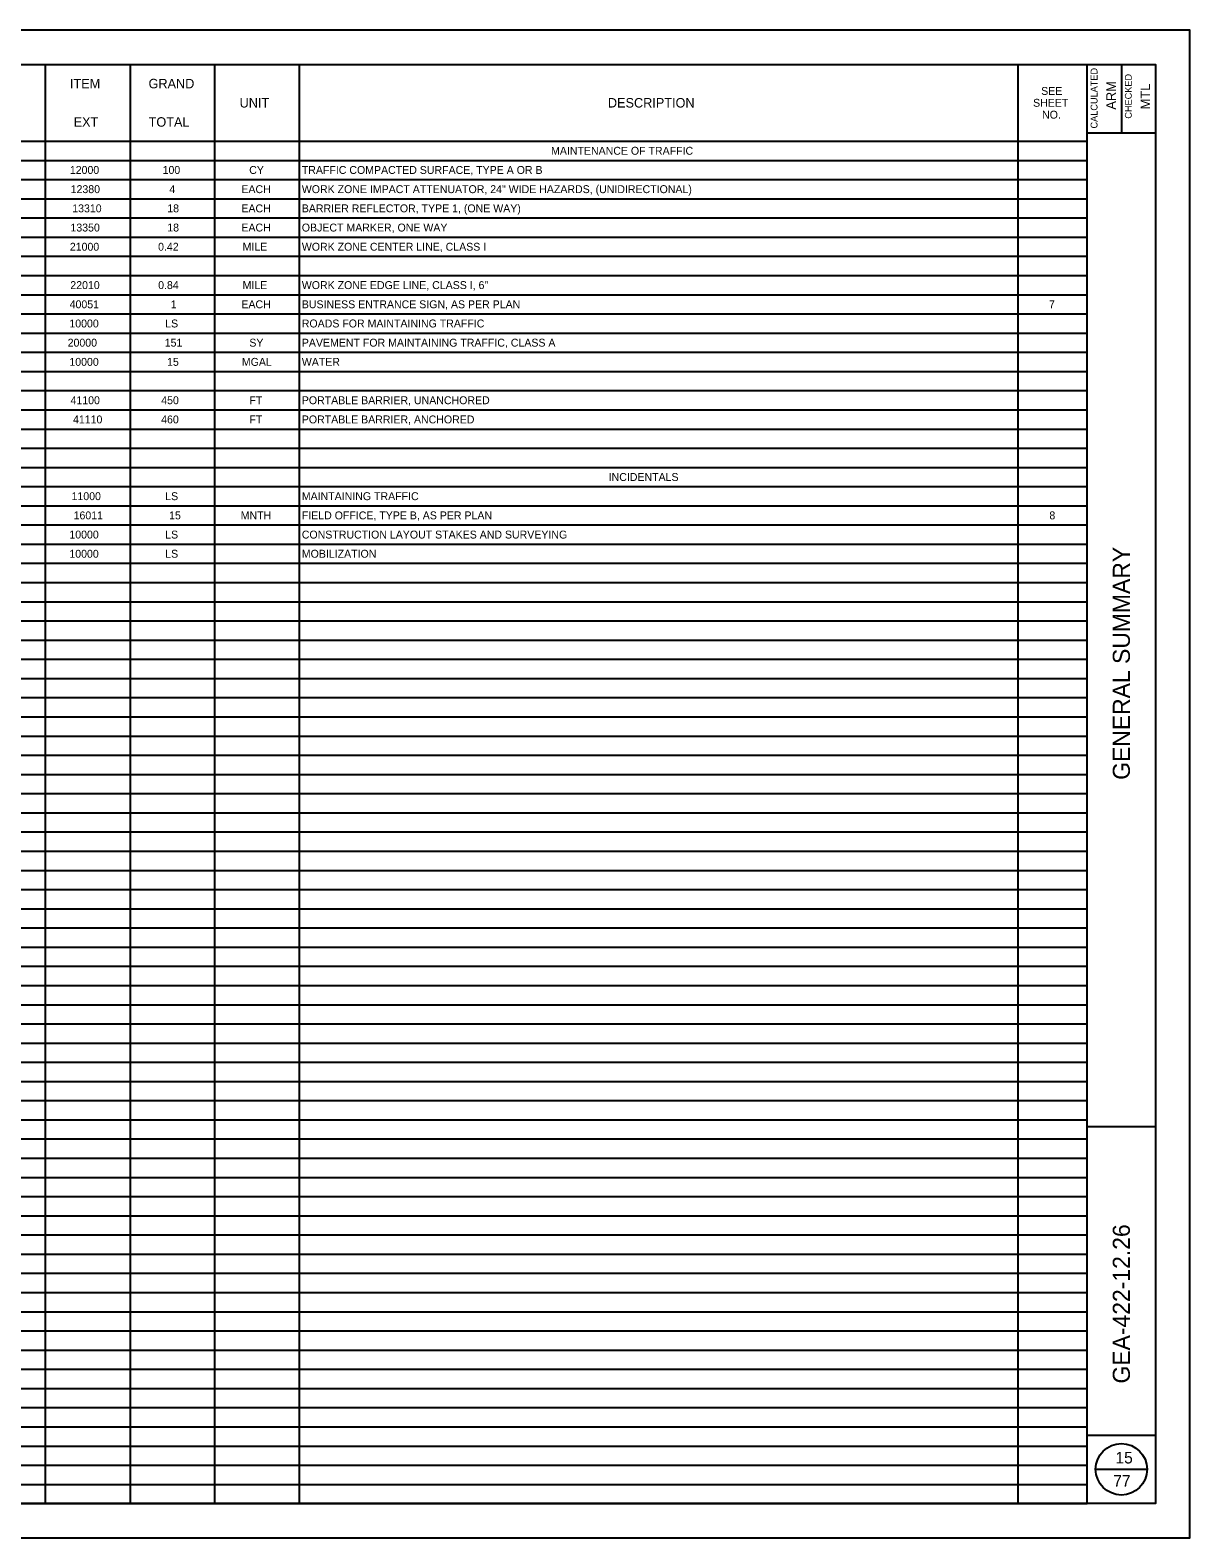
# Model space of a CAD drawing. Extents: x 0 to 34, y 0 to 23.1.
# Drawn here: x 17.07 to 34, y 0 to 22 of the extents above; entities that cross this region are included whole.
import ezdxf

# ---------------------------------------------------------------- set-up
doc = ezdxf.new("R2010")
doc.units = 0
for name, color, linetype in [('SH_Border', 7, 'Continuous'), ('SH_Cut_Line', 7, 'Continuous'), ('SH_Data', 7, 'Continuous'), ('SH_Text', 7, 'Continuous')]:
    doc.layers.add(name, color=color, linetype=linetype)

msp = doc.modelspace()

# ---------------------------------------------------------------- linework, layer by layer
at = {"layer": 'SH_Border'}
for p, q in [((32.5, 0.5), (32.5, 21.5)), ((33, 21.5), (33, 20.5)), ((32.5, 20.5), (33.5, 20.5)), ((32.5, 6), (33.5, 6)), ((32.5, 1.5), (33.5, 1.5))]:
    msp.add_line(p, q, dxfattribs=at)
msp.add_lwpolyline([(2, 21.5), (33.5, 21.5), (33.5, 0.5), (2, 0.5)], close=True, dxfattribs=at)
at = {"layer": 'SH_Cut_Line'}
msp.add_lwpolyline([(0, 0), (34, 0), (34, 22), (0, 22)], close=True, dxfattribs=at)
at = {"layer": 'SH_Data'}
msp.add_line((32.625, 1), (33.375, 1), dxfattribs=at)
msp.add_circle((33, 1), 0.375, dxfattribs=at)
at = {"layer": 'SH_Text'}
for p, q in [((2, 21.5), (32.5, 21.5)), ((17.299, 0.5), (17.299, 21.5)), ((18.535, 0.5), (18.535, 21.5)), ((19.77, 0.5), (19.77, 21.5)), ((21.005, 0.5), (21.005, 21.5)), ((31.495, 0.5), (31.495, 21.5)), ((32.5, 0.5), (32.5, 21.5)), ((14.055, 20.38), (32.5, 20.38)), ((19.77, 20.38), (32.5, 20.38)), ((2, 20.1), (32.5, 20.1)), ((2, 19.82), (32.5, 19.82)), ((2, 19.54), (32.5, 19.54)), ((2, 19.26), (32.5, 19.26)), ((2, 18.98), (32.5, 18.98)), ((2, 18.7), (32.5, 18.7)), ((2, 18.42), (32.5, 18.42)), ((2, 18.14), (32.5, 18.14)), ((2, 17.86), (32.5, 17.86)), ((2, 17.58), (32.5, 17.58)), ((2, 17.3), (32.5, 17.3)), ((2, 17.02), (32.5, 17.02)), ((2, 16.74), (32.5, 16.74)), ((2, 16.46), (32.5, 16.46)), ((2, 16.18), (32.5, 16.18)), ((2, 15.9), (32.5, 15.9)), ((2, 15.62), (32.5, 15.62)), ((2, 15.34), (32.5, 15.34)), ((2, 15.06), (32.5, 15.06)), ((2, 14.78), (32.5, 14.78)), ((2, 14.5), (32.5, 14.5)), ((2, 14.22), (32.5, 14.22)), ((2, 13.94), (32.5, 13.94)), ((2, 13.66), (32.5, 13.66)), ((2, 13.38), (32.5, 13.38)), ((2, 13.1), (32.5, 13.1)), ((2, 12.82), (32.5, 12.82)), ((2, 12.54), (32.5, 12.54)), ((2, 12.26), (32.5, 12.26)), ((2, 11.98), (32.5, 11.98)), ((2, 11.7), (32.5, 11.7)), ((2, 11.42), (32.5, 11.42)), ((2, 11.14), (32.5, 11.14)), ((2, 10.86), (32.5, 10.86)), ((2, 10.58), (32.5, 10.58)), ((2, 10.3), (32.5, 10.3)), ((2, 10.02), (32.5, 10.02)), ((2, 9.74), (32.5, 9.74)), ((2, 9.46), (32.5, 9.46)), ((2, 9.18), (32.5, 9.18)), ((2, 8.9), (32.5, 8.9)), ((2, 8.62), (32.5, 8.62)), ((2, 8.34), (32.5, 8.34)), ((2, 8.06), (32.5, 8.06)), ((2, 7.78), (32.5, 7.78)), ((2, 7.5), (32.5, 7.5)), ((2, 7.22), (32.5, 7.22)), ((2, 6.94), (32.5, 6.94)), ((2, 6.66), (32.5, 6.66)), ((2, 6.38), (32.5, 6.38)), ((2, 6.1), (32.5, 6.1)), ((2, 5.82), (32.5, 5.82)), ((2, 5.54), (32.5, 5.54)), ((2, 5.26), (32.5, 5.26)), ((2, 4.98), (32.5, 4.98)), ((2, 4.7), (32.5, 4.7)), ((2, 4.42), (32.5, 4.42)), ((2, 4.14), (32.5, 4.14)), ((2, 3.86), (32.5, 3.86)), ((2, 3.58), (32.5, 3.58)), ((2, 3.3), (32.5, 3.3)), ((2, 3.02), (32.5, 3.02)), ((2, 2.74), (32.5, 2.74)), ((2, 2.46), (32.5, 2.46)), ((2, 2.18), (32.5, 2.18)), ((2, 1.9), (32.5, 1.9)), ((2, 1.62), (32.5, 1.62)), ((2, 1.34), (32.5, 1.34)), ((2, 1.06), (32.5, 1.06)), ((2, 0.78), (32.5, 0.78)), ((2, 0.5), (32.5, 0.5))]:
    msp.add_line(p, q, dxfattribs=at)

# ---------------------------------------------------------------- texts
at = {"layer": 'SH_Data'}
for s, height, p in [('CALCULATED', 0.1, (32.652, 20.565)), ('CHECKED', 0.1, (33.152, 20.708)), ('ARM', 0.14, (32.92, 20.84)), ('MTL', 0.14, (33.42, 20.844)), ('GENERAL SUMMARY', 0.25, (33.125, 11.061)), ('GEA-422-12.26', 0.25, (33.125, 2.252))]:
    msp.add_text(s, height=height, rotation=90, dxfattribs=at).set_placement(p)
for s, p in [('15', (32.914, 1.085)), ('77', (32.882, 0.745))]:
    msp.add_text(s, height=0.17, dxfattribs=at).set_placement(p)
at = {"layer": 'SH_Text'}
for s, height, p in [('ITEM', 0.1384, (17.654, 21.151)), ('GRAND', 0.1384, (18.801, 21.151)), ('SEE', 0.1153, (31.83, 21.055)), ('UNIT', 0.1384, (20.13, 20.871)), ('DESCRIPTION', 0.13841, (25.506, 20.871)), ('SHEET', 0.1153, (31.712, 20.882)), ('EXT', 0.1384, (17.707, 20.591)), ('TOTAL', 0.1384, (18.802, 20.591)), ('NO.', 0.1153, (31.843, 20.709)), ('MAINTENANCE OF TRAFFIC', 0.11534, (24.676, 20.182)), ('12000', 0.1153, (17.652, 19.902)), ('100', 0.1153, (19.006, 19.902)), ('CY', 0.1153, (20.27, 19.902)), ('TRAFFIC COMPACTED SURFACE, TYPE A OR B ', 0.11534, (21.038, 19.902)), ('12380', 0.1153, (17.664, 19.622)), ('12380', 0.1153, (17.664, 19.622)), ('4', 0.115, (19.104, 19.622)), ('EACH', 0.1153, (20.156, 19.622)), ('WORK ZONE IMPACT ATTENUATOR, 24" WIDE HAZARDS, (UNIDIRECTIONAL) ', 0.11534, (21.038, 19.622)), ('WORK ZONE IMPACT ATTENUATOR, 24" WIDE HAZARDS, (UNIDIRECTIONAL) ', 0.11534, (21.038, 19.622)), ('13310', 0.1153, (17.687, 19.342)), ('18', 0.1153, (19.074, 19.342)), ('EACH', 0.1153, (20.156, 19.342)), ('BARRIER REFLECTOR, TYPE 1, (ONE WAY)', 0.11534, (21.038, 19.342)), ('BARRIER REFLECTOR, TYPE 1, (ONE WAY)', 0.11534, (21.038, 19.342)), ('13350', 0.1153, (17.661, 19.062)), ('18', 0.1153, (19.074, 19.062)), ('EACH', 0.1153, (20.156, 19.062)), ('OBJECT MARKER, ONE WAY ', 0.11534, (21.038, 19.062)), ('21000', 0.1153, (17.652, 18.782)), ('0.42', 0.1153, (18.94, 18.782)), ('MILE', 0.1153, (20.174, 18.782)), ('WORK ZONE CENTER LINE, CLASS I ', 0.11534, (21.038, 18.782)), ('22010', 0.1153, (17.659, 18.222)), ('0.84', 0.1153, (18.941, 18.222)), ('MILE', 0.1153, (20.174, 18.222)), ('WORK ZONE EDGE LINE, CLASS I, 6" ', 0.11534, (21.038, 18.222)), ('40051', 0.1153, (17.649, 17.942)), ('1', 0.115, (19.125, 17.942)), ('EACH', 0.1153, (20.156, 17.942)), ('BUSINESS ENTRANCE SIGN, AS PER PLAN ', 0.11534, (21.038, 17.942)), ('7', 0.115, (31.944, 17.942)), ('10000', 0.1153, (17.645, 17.662)), ('LS', 0.1153, (19.044, 17.662)), ('ROADS FOR MAINTAINING TRAFFIC', 0.11534, (21.038, 17.662)), ('20000', 0.1153, (17.62, 17.382)), ('151', 0.1153, (19.037, 17.382)), ('SY', 0.1153, (20.272, 17.382)), ('PAVEMENT FOR MAINTAINING TRAFFIC, CLASS A ', 0.11534, (21.038, 17.382)), ('10000', 0.1153, (17.645, 17.102)), ('15', 0.1153, (19.071, 17.102)), ('MGAL', 0.1153, (20.163, 17.102)), ('WATER ', 0.1153, (21.038, 17.102)), ('41100', 0.1153, (17.662, 16.542)), ('450', 0.1153, (18.986, 16.542)), ('FT', 0.1153, (20.272, 16.542)), ('PORTABLE BARRIER, UNANCHORED', 0.11534, (21.038, 16.542)), ('41110', 0.1153, (17.698, 16.262)), ('460', 0.1153, (18.985, 16.262)), ('FT', 0.1153, (20.272, 16.262)), ('PORTABLE BARRIER, ANCHORED', 0.11534, (21.038, 16.262)), ('INCIDENTALS', 0.11534, (25.517, 15.422)), ('11000', 0.1153, (17.677, 15.142)), ('LS', 0.1153, (19.044, 15.142)), ('MAINTAINING TRAFFIC', 0.11534, (21.038, 15.142)), ('16011', 0.1153, (17.707, 14.862)), ('15', 0.1153, (19.101, 14.862)), ('15', 0.1153, (19.101, 14.862)), ('MNTH', 0.1153, (20.146, 14.862)), ('FIELD OFFICE, TYPE B, AS PER PLAN', 0.11534, (21.038, 14.862)), ('FIELD OFFICE, TYPE B, AS PER PLAN', 0.11534, (21.038, 14.862)), ('8', 0.115, (31.95, 14.862)), ('10000', 0.1153, (17.645, 14.582)), ('LS', 0.1153, (19.044, 14.582)), ('CONSTRUCTION LAYOUT STAKES AND SURVEYING', 0.11534, (21.038, 14.582)), ('10000', 0.1153, (17.645, 14.302)), ('LS', 0.1153, (19.044, 14.302)), ('MOBILIZATION', 0.11534, (21.038, 14.302))]:
    msp.add_text(s, height=height, dxfattribs=at).set_placement(p)

doc.saveas('drawing.dxf')
